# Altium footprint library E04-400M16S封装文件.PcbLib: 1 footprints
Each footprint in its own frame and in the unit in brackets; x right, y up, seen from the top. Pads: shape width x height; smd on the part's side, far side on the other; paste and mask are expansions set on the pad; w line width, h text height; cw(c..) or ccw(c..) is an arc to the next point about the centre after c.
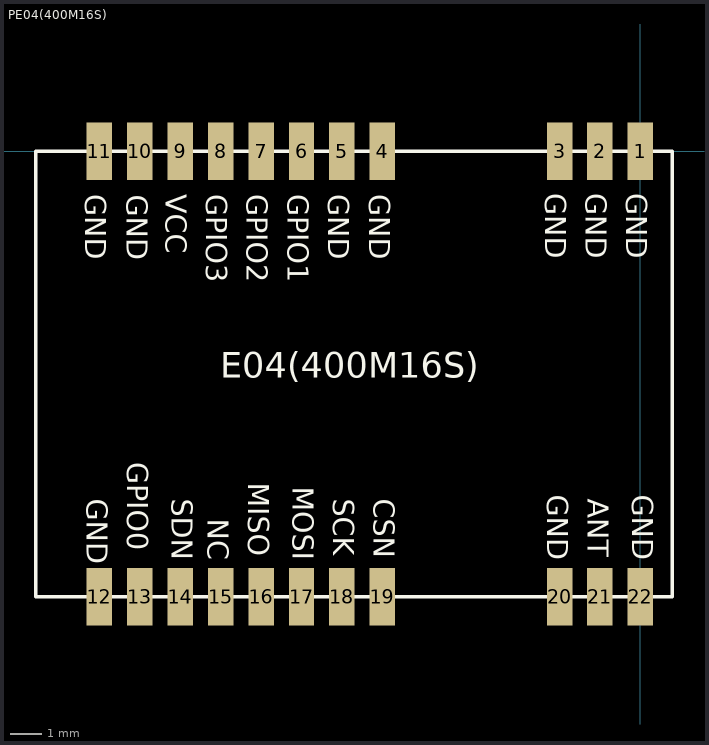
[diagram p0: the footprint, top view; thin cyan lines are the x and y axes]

## PE04(400M16S) [mm] "20mm*14mm*2.8mm-S"
pads (22):
  rect 0.8x1.8 smd: 1(0,0) 2(-1.27,0) 3(-2.54,0) 4(-8.11,0) 5(-9.38,0) 6(-10.65,0) 7(-11.92,0) 8(-13.19,0) 9(-14.46,0) 10(-15.73,0) 11(-17,0) 12(-17,-14) 13(-15.73,-14) 14(-14.46,-14) 15(-13.19,-14) 16(-11.92,-14) 17(-10.65,-14) 18(-9.38,-14) 19(-8.11,-14) 20(-2.54,-14) 21(-1.27,-14) 22(0,-14)
Top Overlay:
  lines w0.1: -19,-14 -19,0 1,0 1,-14 -19,-14
  text "GND" at -8.528,-1.353 h0.65
  text "GND" at -9.807,-1.353 h0.65
  text "GPIO1" at -11.086,-1.353 h0.65
  text "GPIO2" at -12.364,-1.353 h0.65
  text "GPIO3" at -13.643,-1.353 h0.65
  text "VCC" at -14.922,-1.353 h0.65
  text "GND" at -16.14,-1.373 h0.65
  text "GND" at -17.45,-1.353 h0.65
  text "GND" at -2.996,-1.323 h0.65
  text "GND" at -1.717,-1.323 h0.65
  text "GND" at -0.438,-1.323 h0.65
  text "GND" at -0.254,-10.795 h0.65
  text "ANT" at -1.651,-10.922 h0.65
  text "GND" at -2.921,-10.795 h0.65
  text "GND" at -17.399,-10.922 h0.65
  text "GPIO0" at -16.129,-9.779 h0.65
  text "SDN" at -14.732,-10.922 h0.65
  text "NC" at -13.589,-11.557 h0.65
  text "MISO" at -12.319,-10.414 h0.65
  text "MOSI" at -10.922,-10.541 h0.65
  text "SCK" at -9.652,-10.922 h0.65
  text "CSN" at -8.382,-10.922 h0.65
  text "E04(400M16S)" at -13.208,-7.112 h0.8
